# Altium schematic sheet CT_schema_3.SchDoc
size 493 x 398 mm
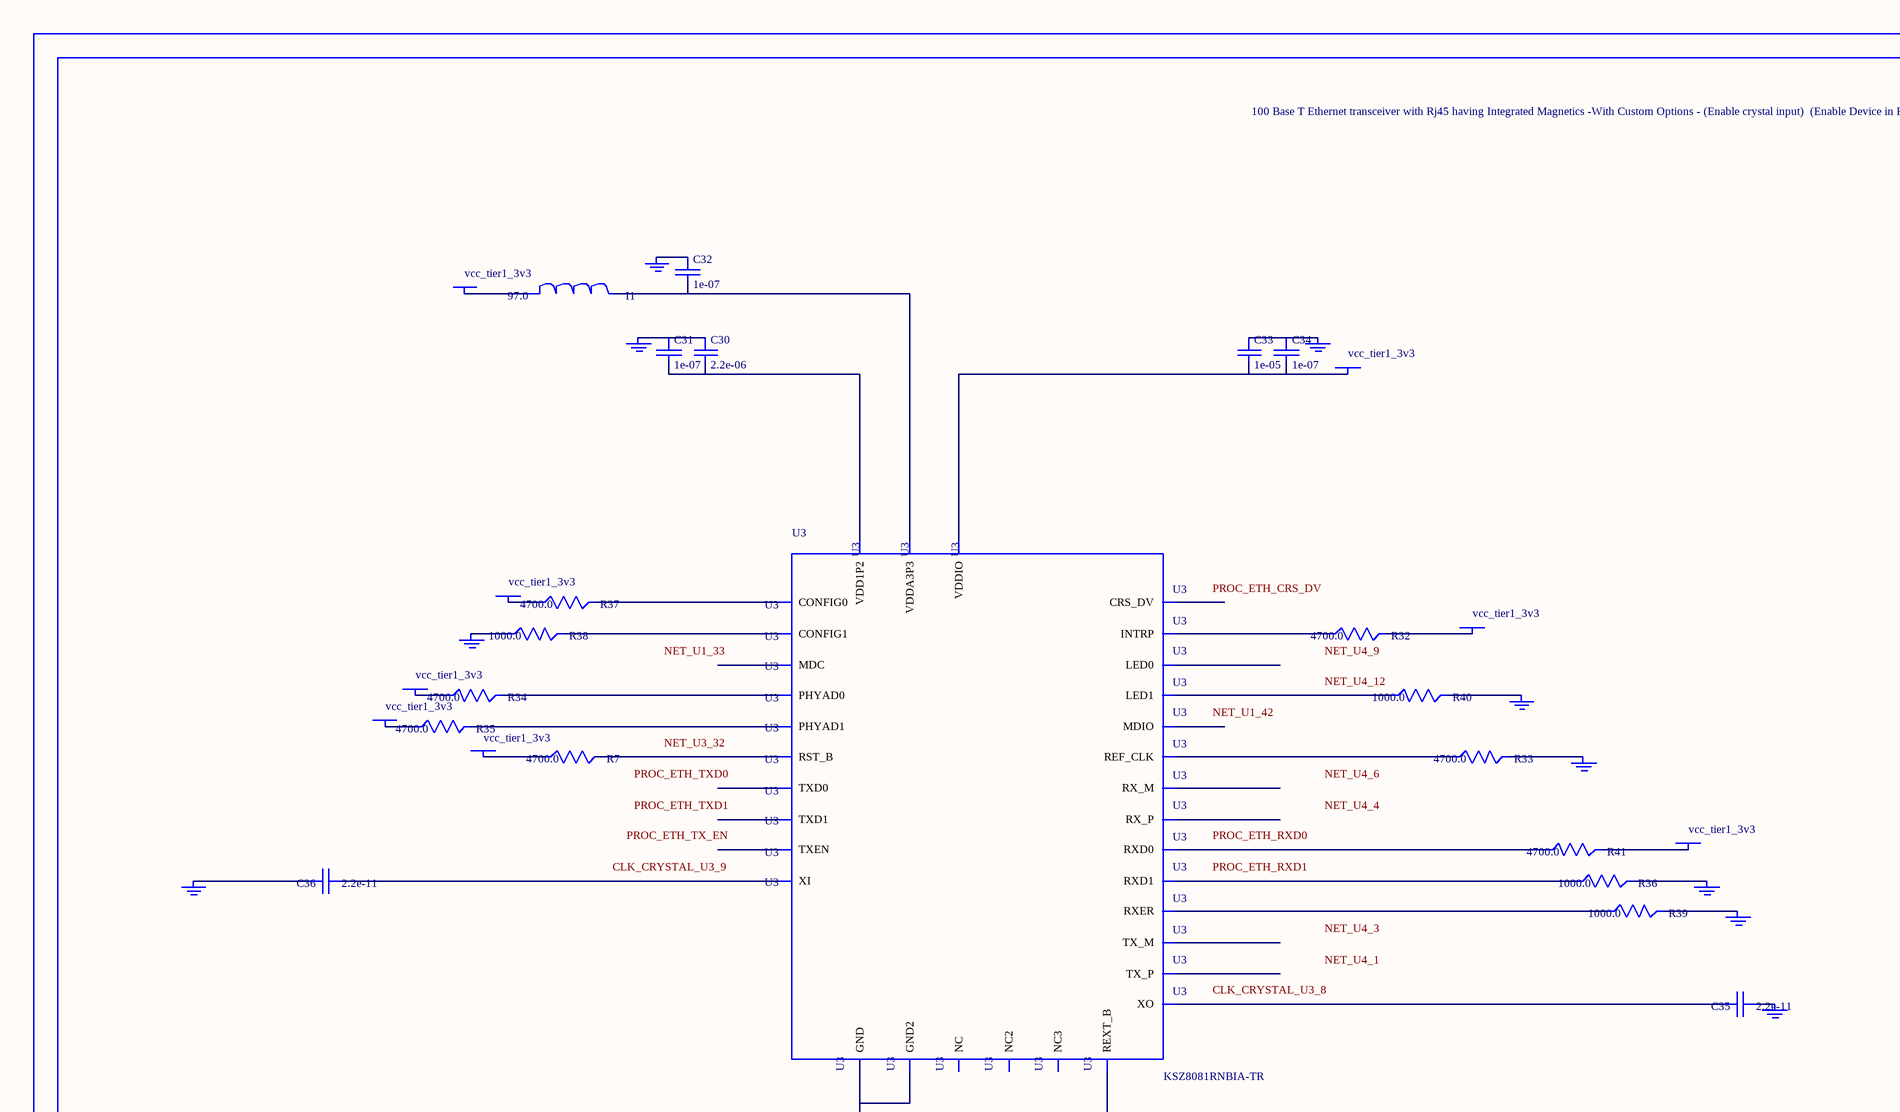
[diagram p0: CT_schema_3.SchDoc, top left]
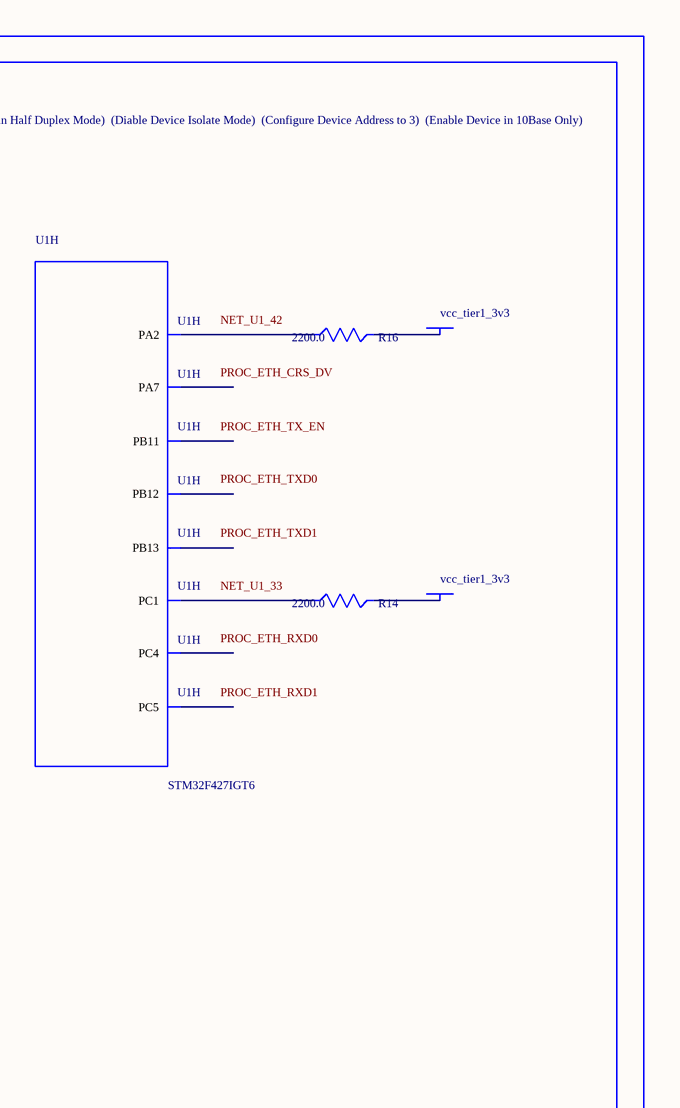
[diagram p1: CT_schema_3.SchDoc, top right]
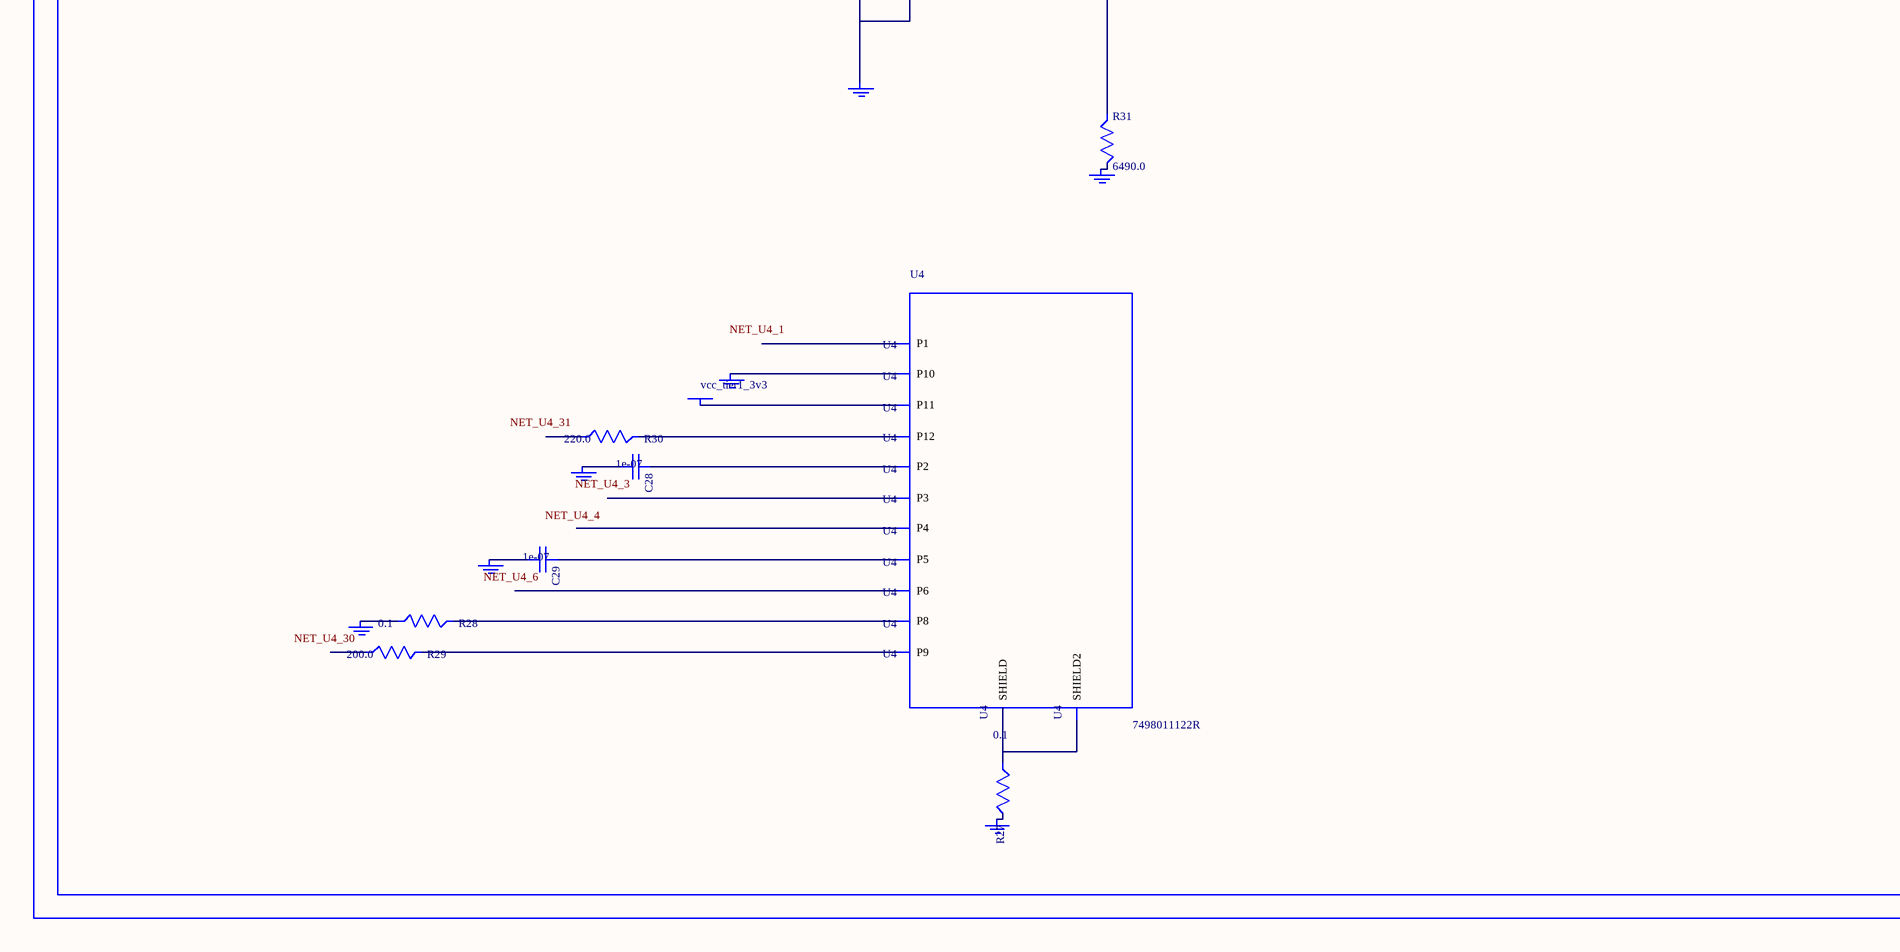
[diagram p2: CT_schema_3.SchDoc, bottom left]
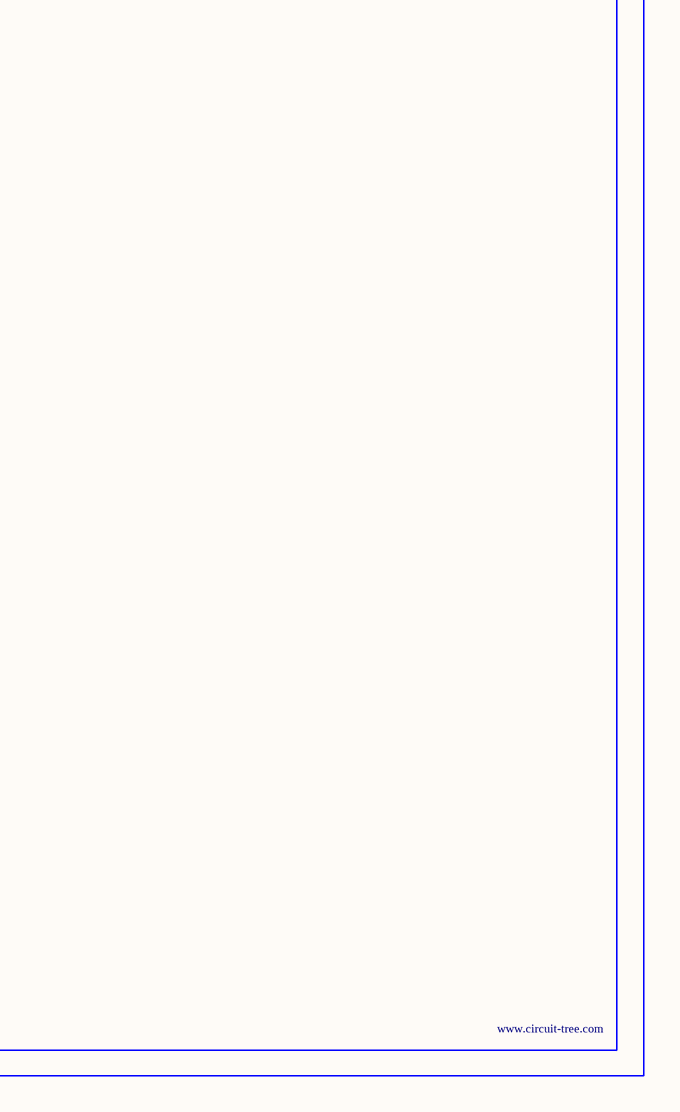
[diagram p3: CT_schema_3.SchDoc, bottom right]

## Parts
BORDER2  (no value)
C28  1e-07  [C0402]
C29  1e-07  [C0402]
C30  2.2e-06  [C0603]
C31  1e-07  [C0402]
C32  1e-07  [C0402]
C33  1e-05  [C0805]
C34  1e-07  [C0402]
C35  2.2e-11  [C0402]
C36  2.2e-11  [C0402]
GND_INSTANCE_2_0  (no value)
GND_INSTANCE_2_1  (no value)
GND_INSTANCE_2_2  (no value)
GND_INSTANCE_2_3  (no value)
GND_INSTANCE_2_4  (no value)
GND_INSTANCE_2_5  (no value)
GND_INSTANCE_2_6  (no value)
GND_INSTANCE_2_7  (no value)
GND_INSTANCE_2_8  (no value)
GND_INSTANCE_2_9  (no value)
GND_INSTANCE_2_10  (no value)
GND_INSTANCE_2_11  (no value)
GND_INSTANCE_2_12  (no value)
GND_INSTANCE_2_13  (no value)
GND_INSTANCE_2_14  (no value)
GND_INSTANCE_2_15  (no value)
GND_INSTANCE_2_16  (no value)
I1  97.0  [R0603]
POWER_INSTANCE_2_0  vcc_tier1_3v3
POWER_INSTANCE_2_1  vcc_tier1_3v3
POWER_INSTANCE_2_2  vcc_tier1_3v3
POWER_INSTANCE_2_3  vcc_tier1_3v3
POWER_INSTANCE_2_4  vcc_tier1_3v3
POWER_INSTANCE_2_5  vcc_tier1_3v3
POWER_INSTANCE_2_6  vcc_tier1_3v3
POWER_INSTANCE_2_7  vcc_tier1_3v3
POWER_INSTANCE_2_8  vcc_tier1_3v3
POWER_INSTANCE_2_9  vcc_tier1_3v3
POWER_INSTANCE_2_10  vcc_tier1_3v3
R7  4700.0  [R0603]
R14  2200.0  [R0603]
R16  2200.0  [R0603]
R27  0.1  [R0603]
R28  0.1  [R0603]
R29  200.0  [R0603]
R30  220.0  [R0603]
R31  6490.0  [R0603]
R32  4700.0  [R0603]
R33  4700.0  [R0603]
R34  4700.0  [R0603]
R35  4700.0  [R0603]
R36  1000.0  [R0603]
R37  4700.0  [R0603]
R38  1000.0  [R0603]
R39  1000.0  [R0603]
R40  1000.0  [R0603]
R41  4700.0  [R0603]
U1  STM32F427IGT6  [LQFP176]  (part H of 14)
U3  KSZ8081RNBIA-TR  [QFN-32]
U4  7498011122R  [7498011122R]

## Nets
NetC28_1: C28.1 U4.2(P2)
NetC28_2: C28.2 GND_INSTANCE_2_12.0(GND)
NetC29_1: C29.1 U4.5(P5)
NetC29_2: C29.2 GND_INSTANCE_2_13.0(GND)
NetC30_1: C30.1 C31.1 GND_INSTANCE_2_0.0(GND)
NetC30_2: C30.2 C31.2 U3.2(VDD1P2)
NetC32_1: C32.1 GND_INSTANCE_2_1.0(GND)
NetC32_2: C32.2 I1.2 U3.3(VDDA3P3)
NetC33_1: C33.1 C34.1 GND_INSTANCE_2_6.0(GND)
NetC33_2: C33.2 C34.2 POWER_INSTANCE_2_4.0(PWR) U3.17(VDDIO)
NetC35_1: C35.1 GND_INSTANCE_2_2.0(GND)
NetC35_2: C35.2 U3.8(XO)
NetC36_1: C36.1 U3.9(XI)
NetC36_2: C36.2 GND_INSTANCE_2_3.0(GND)
NetGND_INSTANCE_2_4_0: GND_INSTANCE_2_4.0(GND) R31.2
NetGND_INSTANCE_2_5_0: GND_INSTANCE_2_5.0(GND) R36.2
NetGND_INSTANCE_2_7_0: GND_INSTANCE_2_7.0(GND) R33.2
NetGND_INSTANCE_2_8_0: GND_INSTANCE_2_8.0(GND) R39.2
NetGND_INSTANCE_2_9_0: GND_INSTANCE_2_9.0(GND) R38.1
NetGND_INSTANCE_2_10_0: GND_INSTANCE_2_10.0(GND) R40.2
NetGND_INSTANCE_2_11_0: GND_INSTANCE_2_11.0(GND) U3.1(GND) U3.EXP(GND2)
NetGND_INSTANCE_2_14_0: GND_INSTANCE_2_14.0(GND) R28.1
NetGND_INSTANCE_2_15_0: GND_INSTANCE_2_15.0(GND) U4.10(P10)
NetGND_INSTANCE_2_16_0: GND_INSTANCE_2_16.0(GND) R27.2
NetI1_1: I1.1 POWER_INSTANCE_2_0.0(PWR)
NetPOWER_INSTANCE_2_1_0: POWER_INSTANCE_2_1.0(PWR) R34.1
NetPOWER_INSTANCE_2_2_0: POWER_INSTANCE_2_2.0(PWR) R35.1
NetPOWER_INSTANCE_2_3_0: POWER_INSTANCE_2_3.0(PWR) R41.2
NetPOWER_INSTANCE_2_5_0: POWER_INSTANCE_2_5.0(PWR) R32.2
NetPOWER_INSTANCE_2_6_0: POWER_INSTANCE_2_6.0(PWR) R37.1
NetPOWER_INSTANCE_2_7_0: POWER_INSTANCE_2_7.0(PWR) R7.1
NetPOWER_INSTANCE_2_8_0: POWER_INSTANCE_2_8.0(PWR) R14.2
NetPOWER_INSTANCE_2_9_0: POWER_INSTANCE_2_9.0(PWR) R16.2
NetPOWER_INSTANCE_2_10_0: POWER_INSTANCE_2_10.0(PWR) U4.11(P11)
NetR7_2: R7.2 U3.32(RST_B)
NetR14_1: R14.1 U1.33(PC1)
NetR16_1: R16.1 U1.42(PA2)
NetR27_1: R27.1 U4.13(SHIELD) U4.14(SHIELD2)
NetR28_2: R28.2 U4.8(P8)
NetR29_2: R29.2 U4.9(P9)
NetR30_2: R30.2 U4.12(P12)
NetR31_1: R31.1 U3.10(REXT_B)
NetR32_1: R32.1 U3.21(INTRP)
NetR33_1: R33.1 U3.19(REF_CLK)
NetR34_2: R34.2 U3.13(PHYAD0)
NetR35_2: R35.2 U3.14(PHYAD1)
NetR36_1: R36.1 U3.15(RXD1)
NetR37_2: R37.2 U3.28(CONFIG0)
NetR38_2: R38.2 U3.29(CONFIG1)
NetR39_1: R39.1 U3.20(RXER)
NetR40_1: R40.1 U3.31(LED1)
NetR41_1: R41.1 U3.16(RXD0)

Not connected (* = marked no-connect by the designer): R29 1; R30 1; U1 53(PA7) 54(PC4) 55(PC5) 80(PB11) 92(PB12) 93(PB13); U3 4(RX_M) 5(RX_P) 6(TX_M) 7(TX_P) 11(MDIO) 12(MDC) 18(CRS_DV) 22(NC) 23(TXEN) 24(TXD0) 25(TXD1) 26(NC2) 27(NC3) 30(LED0); U4 1(P1) 3(P3) 4(P4) 6(P6)

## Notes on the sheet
- Labels drawn without touching a wire or pin: CLK_CRYSTAL_U3_8, CLK_CRYSTAL_U3_9, NET_U1_33, NET_U1_42, NET_U3_32, NET_U4_1, NET_U4_3, NET_U4_4, NET_U4_6, NET_U4_9, NET_U4_12, NET_U4_30, NET_U4_31, PROC_ETH_CRS_DV, PROC_ETH_RXD0, PROC_ETH_RXD1, PROC_ETH_TX_EN, PROC_ETH_TXD0, PROC_ETH_TXD1

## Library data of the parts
BORDER2 = BORDER_PAGE2
C28 C29 C31 C32 C34 = C0402C104K3RACTU
C30 = C0603C225K8RACTU
C33 = C0805C106K8RACTU
C35 C36 = C0402C220K3RAC
GND_INSTANCE_2_0-GND_INSTANCE_2_16 = GND
I1 = I1
POWER_INSTANCE_2_0-POWER_INSTANCE_2_10 = PWR
R7 R32-R35 R37 R41 = RC0603JR-074K7L
R14 R16 = RC0603JR-072K2L
R27 R28 = ERJ-3RSFR10V
R29 = RC0603JR-07200RL
R30 = RC0603JR-07220RL
R31 = ERJ-3EKF6491V
R36 R38-R40 = RC0603JR-071KL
